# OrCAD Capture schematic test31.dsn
size A
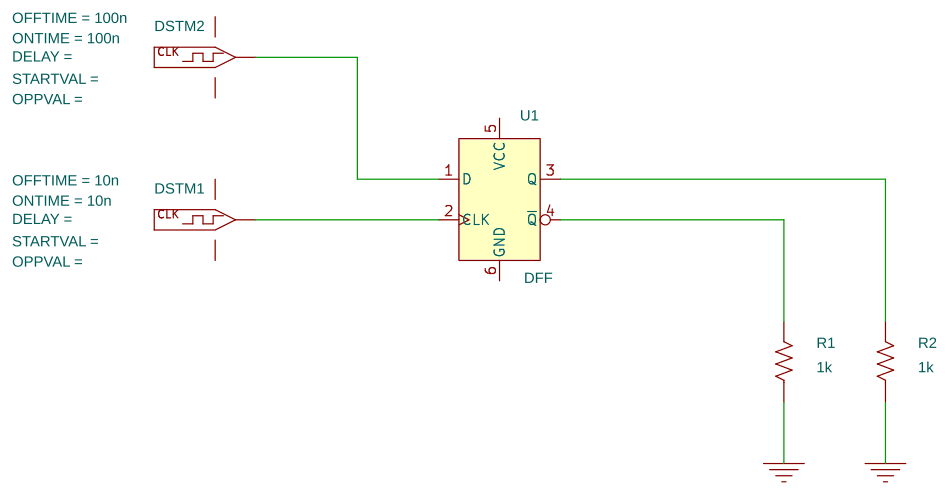
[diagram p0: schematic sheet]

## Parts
DSTM1  DigClock
DSTM2  DigClock
R1  1k  [AXRC05]
R2  1k  [AXRC05]
U1  DFF

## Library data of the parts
DSTM1 = DigClock: OFFTIME: 10n; ONTIME: 10n
DSTM2 = DigClock: OFFTIME: 100n; ONTIME: 100n
R1 R2 = R
U1 = DFF

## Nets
GND: DSTM1.3(GND) DSTM2.3(GND) U1.6(GND)
VCC: DSTM1.2(VCC) DSTM2.2(VCC) U1.5(VCC)
0: R1.1 R2.1
N00309: DSTM2.1 U1.1(D)
N00388: R2.2 U1.3(Q)
N00400: R1.2 U1.4(~{Q})
N00763: DSTM1.1 U1.2(CLK)
